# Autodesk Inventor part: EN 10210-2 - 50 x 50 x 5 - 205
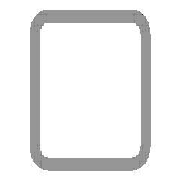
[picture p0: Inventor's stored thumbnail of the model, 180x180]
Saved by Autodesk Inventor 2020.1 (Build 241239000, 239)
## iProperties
_CCFamilyMember: 16
_CCFamilyDisplayName: DIN EN 10210-2 (USAS B17.1 quadratisch) - Rohrleitung — In Klammern angegebene Größen wurden aufgehoben
_FrameMemberDoc: Frame Member File
_Version: 15.0.0
_GetPNFromCC: 1
IsCustomPart: 1
Created: 2019-10
Part Number: EN 10210-2 - 50 x 50 x 5 - 205
Material: Stahl, weich
Description: Rohrleitung
Document SubType Name: Modeling
Standard: DIN
Designer: lutzd
Standard Revision: 2006-07
Standards Organization: DIN
Language: de-DE
Size Designation: 50 x 50 x 5
Categories: <MemberInstance><Categories><Category DisplayName="Profile" InternalName="089c4875-fa83-4c05-b084-43b9cc11f5ed" Mnemonic="GRDR"><CategoryParameter DisplayName="
Stock Number: 50 x 50 x 5
Mass: 1405.16 g
Surface Area: 711.47 cm^2
Volume: 179.001 cm^3
Density: 7.85 g/cm^3
Appearance: Halbpoliert
G_W: 50,000 mm
G_H: 50,000 mm
Dimensions: 50x50x205 mm
Mass: 1,405 kg
G_L: 205,000 mm
DocNumber: ADSK-014175
Folder: .
Title: Profil-Bauteil
Author: lutzd
Revision Number: -
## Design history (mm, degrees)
node "Startebene"
node "Endebene"
sketch "Skizze"
  geometry: L1 (-25, -17.5)-(-25, 17.5); L2 (-17.5, 25)-(17.5, 25); L3 (25, 17.5)-(25, -17.5); L4 (17.5, -25)-(-17.5, -25); L5 (-15, 20)-(15, 20); L6 (20, 15)-(20, -15); L7 (15, -20)-(-15, -20); L8 (-20, -15)-(-20, 15); L9 (0, 37.175)-(0, -37.175) reference; L10 (-37.175, 0)-(37.175, 0) reference; A1 r 7.5 centre (-17.5, -17.5) between (-25, -17.5) and (-17.5, -25); A2 r 7.5 centre (-17.5, 17.5) between (-17.5, 25) and (-25, 17.5); A3 r 7.5 centre (17.5, 17.5) between (25, 17.5) and (17.5, 25); A4 r 7.5 centre (17.5, -17.5) between (17.5, -25) and (25, -17.5); A5 r 5 centre (-15, -15) between (-20, -15) and (-15, -20); A6 r 5 centre (-15, 15) between (-15, 20) and (-20, 15); A7 r 5 centre (15, 15) between (20, 15) and (15, 20); A8 r 5 centre (15, -15) between (15, -20) and (20, -15)
  constraints: 16 end point, 16 point on circle, 16 tangent, 8 centre point, 6 equal radius, 4 parallel, 2 perpendicular, 2 other
  dimensions: "d7" = 7.5 radius of A1 (= G_IR); "d10" = 50 distance between parallel lines of L2 L4 (= G_H); "d11" = 50 distance between parallel lines of L1 L3 (= G_W); "d12" = 5 distance between parallel lines of L3 L6 (= G_T); "d15" = 25 distance between parallel lines of L2 L10 (= 0.5 x d10); "d16" = 25 distance between parallel lines of L9 L3 (= 0.5 x d11); "d19" = 5 radius of A5 (= G_T); "d20" = 5 distance between parallel lines of L4 L7 (= G_T)
extrude "Körper" new body sketch "Skizze" stored distance "d3" = 205 (= G_L); taper "d4" = 0 deg
node "Driven Length"
  sketch "Sketch3"
    geometry: L1 (0, 0)-(10, 0) reference
    constraints: 2 end point, 1 horizontal
  workplane "Work Plane3"
  sketch "Sketch4"
    geometry: L1 (-2, 25)-(12, 25) reference; L2 (-2, 230)-(12, 230) reference
    dimensions: "d18" = 205 distance between parallel lines of L1 L2 (derived)
workplane "Arbeitsebene5"
feature "Trennen2"
workplane "Arbeitsebene6"
feature "Trennen3"
body "Solid1"
other parameters: "G_W" = 50 [user parameter; used in 1 equation term], "G_H" = 50 [user parameter; used in 1 equation term], "G_T" = 5 [user parameter; used in 3 equation terms], "G_IR" = 7.5 [user parameter; used in 1 equation term], "G_L" = 205 (= d18) [user parameter; used in 1 equation term], "G_OFFSET_START" = -25 [user parameter; used in 1 equation term], "G_OFFSET_END" = 25 [user parameter; used in 1 equation term], "d13" = 25 (= -G_OFFSET_START), "B_L" = 205 [user parameter; used in 1 equation term], "d17" = 90 deg
